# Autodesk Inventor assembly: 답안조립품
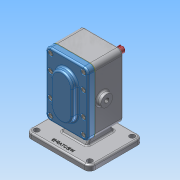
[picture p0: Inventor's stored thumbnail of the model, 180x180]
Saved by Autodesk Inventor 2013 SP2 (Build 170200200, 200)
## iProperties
Created: 2026-10
Part Number: 답안조립품
Document SubType Name: Assembly
Designer: a
Author: a
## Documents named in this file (11)
- C:\Users\a\Desktop\761003V1007\답안조립품.iam
- C:\Users\a\Desktop\761003V1007\본체.ipt
- C:\Users\a\Desktop\761003V1007\6각 구멍붙이 볼트 M5x16.ipt
- C:\Users\a\Desktop\761003V1007\개스킷.ipt
- C:\Users\a\Desktop\761003V1007\구동 축.ipt
- C:\Users\a\Desktop\761003V1007\베어링 부시.ipt
- C:\Users\a\Desktop\761003V1007\스퍼 기어.ipt
- C:\Users\a\Desktop\761003V1007\오일 실 16 28 7.ipt
- C:\Users\a\Desktop\761003V1007\종동 축.ipt
- C:\Users\a\Desktop\761003V1007\커버.ipt
- C:\Users\a\Desktop\761003V1007\평행 키 6x6x18.ipt
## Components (10 placed, 3 different names)
1. 개스킷:1
2. 구동 축:1 — 플러쉬:1
3. 6각 구멍붙이 볼트 M5x16:1
4. 6각 구멍붙이 볼트 M5x16:3
5. 6각 구멍붙이 볼트 M5x16:4
6. 6각 구멍붙이 볼트 M5x16:5
7. 6각 구멍붙이 볼트 M5x16:2
8. 6각 구멍붙이 볼트 M5x16:6
9. 6각 구멍붙이 볼트 M5x16:7
10. 6각 구멍붙이 볼트 M5x16:8
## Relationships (1: Flush 1)
- 플러쉬:1 [Flush]: 구동 축:1
